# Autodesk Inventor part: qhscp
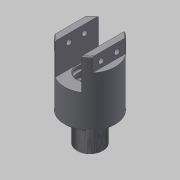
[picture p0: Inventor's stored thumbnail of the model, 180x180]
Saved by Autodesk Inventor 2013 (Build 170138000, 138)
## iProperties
Created: 2019-02
Part Number: qhscp
Material: 일반
Document SubType Name: Modeling
Designer: Gpr
Density: 1 g/cm^3
Author: Gpr
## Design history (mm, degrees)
sketch "스케치1"
  geometry: C1 r 29 at (0, 0)
  constraints: 1 centre point
  dimensions: "d0" = 58 diameter of C1
extrude "돌출1" new body sketch "스케치1" distance "d1" = 74; taper "d2" = 0 deg
chamfer "모따기1" distance "d3" = 1; stored, may be unused: second distance "d4" = 2, angle "d5" = 45 deg
sketch "스케치2"
  geometry: C1 r 28 at (0, 0) reference; C2 r 13 at (0, 0)
  constraints: 1 centre point, 1 coincident
  dimensions: "d6" = 26 diameter of C2
extrude "돌출2" join sketch "스케치2" distance "d7" = 5; taper "d8" = 0 deg
sketch "스케치3"
  geometry: C1 r 13 at (0, 0) reference; C2 r 15 at (0, 0)
  constraints: 1 centre point, 1 coincident
  dimensions: "d9" = 30 diameter of C2
extrude "돌출3" join sketch "스케치3" distance "d10" = 28; taper "d11" = 0 deg
chamfer "모따기2" distance "d12" = 1; stored, may be unused: second distance "d13" = 2, angle "d14" = 45 deg
feature "스레드1" dims "d15" = 10, "d16" = 0
sketch "스케치4"
  geometry: L1 (-15, 29)-(15, 29); L2 (22, 29)-(22, -29); L3 (15, -29)-(-15, -29); L4 (-22, -29)-(-22, 29); L5 (15, -29)-(-15, -29); L6 (-15, -29)-(-15, 29); L7 (-15, 29)-(15, 29); L8 (15, 29)-(15, -29); L9 (22, -29)-(31.478, -29); L10 (31.478, -29)-(31.478, 29); L11 (31.478, 29)-(22, 29); L12 (22, 29)-(22, -29); L13 (-22, -29)-(-30.095, -29); L14 (-30.095, -29)-(-30.095, 29); L15 (-30.095, 29)-(-22, 29); L16 (-22, 29)-(-22, -29); 1 further point
  constraints: 32 end point, 8 parallel, 4 horizontal, 4 perpendicular, 2 midpoint
  dimensions: "d17" = 44 distance of L2.end L4.start; "d18" = 58 distance of L2.start L2.end; "d19" = 30 distance of L1.end L1.start; "d20" = 58 distance of L3.end L1.start
extrude "돌출4" cut sketch "스케치4" distance "d21" = 16; taper "d22" = 0 deg
extrude "돌출5" cut sketch "스케치4" distance "d23" = 36; taper "d24" = 0 deg
sketch "스케치5"
  geometry: L1 (0, 0)-(0, 34.641) reference; L2 (0, 0)-(9, 0); L3 (0, 0)-(9, 0); L4 (0, 17.321)-(0, 8.321); L5 (0, 17.321)-(9, 17.321); C1 r 1.322 at (9, 8.321); C2 r 2.014 at (9, 17.321); C3 r 1.322 at (9, 26.321); 1 further point
  constraints: 8 end point, 3 centre point, 2 equal length, 2 horizontal, 2 perpendicular, 1 coincident, 1 midpoint, 1 symmetric about line, 1 other
  dimensions: "d25" = 9 distance of L1.start L2.end; "d26" = 0 distance between parallel lines of L2 L3 (derived); "d27" = 9 distance of L4.start L4.end; "d28" = 90 deg angle of L4 L5 (derived)
hole "구멍1" sketch "스케치5" at (9, 26.321), (9, 8.321) diameter "d29" = 6; stored, may be unused: countersink angle "d33" = 90 deg, drill point angle "d35" = 0 deg; dims "d30" = 6, "d31" = 4, "d32" = 2, "d34" = 8
hole "구멍2" diameter "d38" = 28; stored, may be unused: countersink angle "d42" = 90 deg, drill point angle "d44" = 0 deg; dims "d39" = 6, "d40" = 28, "d41" = 2.65, "d43" = 2.65, "d80" = 10, "d81" = 10
hole "구멍3" diameter "d49" = 28; stored, may be unused: countersink angle "d53" = 90 deg, drill point angle "d55" = 0 deg; dims "d47" = 10, "d48" = 10, "d50" = 6, "d51" = 34, "d52" = 4.7, "d54" = 9
chamfer "모따기3" distance "d56" = 1; stored, may be unused: second distance "d57" = 2, angle "d58" = 45 deg
fillet "모깎기1" dims "d59" = 0.8
hole "구멍4" diameter "d62" = 28; stored, may be unused: countersink angle "d66" = 90 deg, drill point angle "d68" = 0 deg; dims "d63" = 6, "d64" = 34, "d65" = 4.7, "d67" = 8.35, "d82" = 10, "d83" = 10
fillet "모깎기2" dims "d69" = 0.8
hole "구멍5" diameter "d72" = 32; stored, may be unused: countersink angle "d76" = 90 deg, drill point angle "d78" = 0 deg; dims "d70" = 10, "d71" = 10, "d73" = 6, "d74" = 34, "d75" = 4.7, "d77" = 7
hole "구멍6" diameter "d86" = 8; stored, may be unused: countersink angle "d90" = 90 deg, drill point angle "d92" = 0 deg; dims "d84" = 10, "d85" = 10, "d87" = 6, "d88" = 34, "d89" = 4.7, "d91" = 23
chamfer "모따기4" distance "d93" = 1; stored, may be unused: second distance "d94" = 2, angle "d95" = 45 deg
hole "구멍7" diameter "d98" = 12.376; stored, may be unused: countersink angle "d102" = 90 deg, drill point angle "d104" = 0 deg; dims "d96" = 10, "d97" = 10, "d99" = 18, "d100" = 34, "d101" = 4.7, "d103" = 22
chamfer "모따기5" distance "d105" = 1; stored, may be unused: second distance "d106" = 2, angle "d107" = 45 deg
node "솔리드1"
